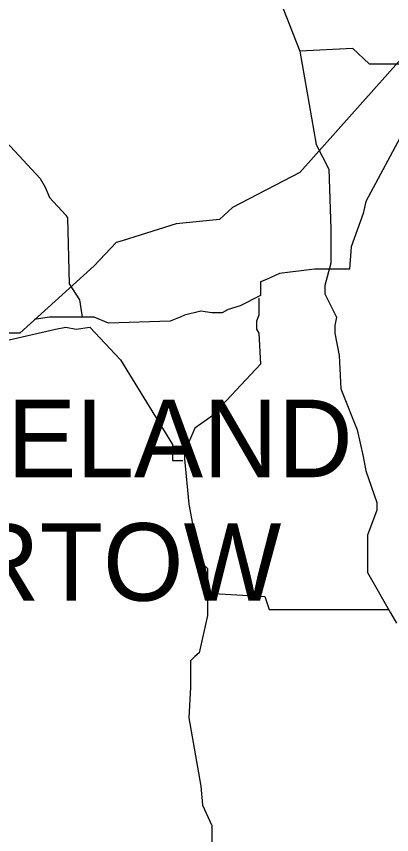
# Model space of a CAD drawing. Extents: x -827.9 to -798.1, y -2199.1 to -2182.2.
# Drawn here: x -806.0075 to -805.7896, y -2184.9111 to -2184.4362 of the extents above; entities that cross this region are included whole.
import ezdxf

# ---------------------------------------------------------------- set-up
doc = ezdxf.new("R2010")
doc.units = 0
for name, color, linetype in [('FLMap2', 7, 'Continuous'), ('FLMap3', 7, 'Continuous'), ('TextMisc', 7, 'Continuous')]:
    doc.layers.add(name, color=color, linetype=linetype)

msp = doc.modelspace()

# ---------------------------------------------------------------- linework, layer by layer
at = {"layer": 'FLMap2'}
for points in [[(-805.94057, -2184.20533), (-805.94057, -2184.22716), (-805.93709, -2184.24006), (-805.9356, -2184.2475), (-805.93015, -2184.25792), (-805.92519, -2184.28223), (-805.92519, -2184.28917), (-805.91576, -2184.2986), (-805.89393, -2184.30455), (-805.88351, -2184.3115), (-805.87408, -2184.35119), (-805.8726, -2184.35615), (-805.86218, -2184.38145), (-805.86218, -2184.38939), (-805.86416, -2184.4003), (-805.85622, -2184.42213), (-805.84283, -2184.45637), (-805.8334, -2184.51044), (-805.82596, -2184.52483), (-805.82497, -2184.55956)], [(-805.72822, -2184.32539), (-805.72227, -2184.33581), (-805.71979, -2184.34176), (-805.71632, -2184.34771), (-805.71632, -2184.36806), (-805.71632, -2184.39435), (-805.71979, -2184.40973), (-805.7188, -2184.47919), (-805.7188, -2184.48415), (-805.72326, -2184.48613), (-805.72475, -2184.49109), (-805.73269, -2184.50151), (-805.75601, -2184.50399), (-805.77734, -2184.49953), (-805.78181, -2184.50151), (-805.80463, -2184.54368), (-805.80612, -2184.55063), (-805.81306, -2184.56998), (-805.81405, -2184.58288), (-805.83439, -2184.58288), (-805.85474, -2184.58536), (-805.86218, -2184.58883)], [(-805.81207, -2184.45488), (-805.84283, -2184.45637)], [(-805.81207, -2184.45488), (-805.80264, -2184.46381), (-805.75452, -2184.46381), (-805.74956, -2184.46728), (-805.7436, -2184.47919), (-805.70937, -2184.47919), (-805.69002, -2184.49358), (-805.68605, -2184.50052)], [(-806.07452, -2184.46976), (-806.0135, -2184.50896), (-805.99365, -2184.53029), (-805.99067, -2184.53525), (-805.98819, -2184.5412), (-805.97877, -2184.55162), (-805.97777, -2184.55311), (-805.97678, -2184.59131)], [(-805.82497, -2184.55956), (-805.82497, -2184.5794), (-805.82844, -2184.5923), (-805.82844, -2184.59727), (-805.8215, -2184.61066), (-805.82249, -2184.61562), (-805.82249, -2184.62009), (-805.82001, -2184.63299), (-805.81902, -2184.65234), (-805.80959, -2184.67615), (-805.80612, -2184.69153), (-805.80463, -2184.69996), (-805.79818, -2184.71832), (-805.79818, -2184.72278), (-805.80364, -2184.73717), (-805.80364, -2184.759), (-805.79024, -2184.78232), (-805.78677, -2184.78827)], [(-805.86218, -2184.58883), (-805.86565, -2184.59032), (-805.86565, -2184.59826), (-805.87756, -2184.60421), (-805.8845, -2184.6062), (-805.88798, -2184.60818), (-805.89393, -2184.60818), (-805.90038, -2184.60719), (-805.90981, -2184.60967), (-805.91229, -2184.61066), (-805.91824, -2184.61314), (-805.95396, -2184.61413), (-805.9624, -2184.61066), (-805.98819, -2184.61066), (-805.99712, -2184.61215)], [(-805.97678, -2184.59131), (-805.97083, -2184.60074), (-805.96934, -2184.61066)], [(-805.86664, -2184.59975), (-805.86664, -2184.60967), (-805.86813, -2184.61314), (-805.86813, -2184.61761), (-805.86664, -2184.62009), (-805.86565, -2184.63795), (-805.89393, -2184.66821), (-805.90385, -2184.67516), (-805.90981, -2184.68905), (-805.90981, -2184.69401)], [(-806.14993, -2184.64291), (-806.14298, -2184.64291), (-806.11173, -2184.63547), (-806.0904, -2184.62852), (-806.04971, -2184.631), (-806.04376, -2184.62951), (-806.03632, -2184.62951), (-805.98472, -2184.61761), (-805.97877, -2184.61661), (-805.97281, -2184.61761), (-805.96488, -2184.61661), (-805.94702, -2184.63547), (-805.91675, -2184.68458), (-805.91675, -2184.69401), (-805.9108, -2184.69401)], [(-805.91675, -2184.68558), (-805.90981, -2184.68558)], [(-805.90981, -2184.69302), (-805.90733, -2184.71931), (-805.90137, -2184.75156), (-805.89641, -2184.75652), (-805.89641, -2184.78381)], [(-805.89641, -2184.77091), (-805.87954, -2184.7719), (-805.86317, -2184.77289), (-805.86069, -2184.78034), (-805.79123, -2184.78034)], [(-805.89641, -2184.78381), (-805.90137, -2184.80564), (-805.90385, -2184.80762), (-805.90633, -2184.8101), (-805.90633, -2184.82548), (-805.90733, -2184.84334), (-805.90038, -2184.88303), (-805.89939, -2184.89395), (-805.89393, -2184.90585), (-805.89393, -2184.95249), (-805.89294, -2184.9644), (-805.89641, -2184.98176), (-805.9108, -2185.01302), (-805.91923, -2185.03832)]]:
    msp.add_lwpolyline(points, dxfattribs=at)
at = {"layer": 'FLMap3'}
for points in [[(-805.57294, -2184.03962), (-805.59179, -2184.04806), (-805.62801, -2184.08874), (-805.64785, -2184.11206), (-805.66968, -2184.18548), (-805.69002, -2184.2088), (-805.71533, -2184.27627), (-805.71284, -2184.32638), (-805.70788, -2184.33482), (-805.71284, -2184.36309), (-805.71632, -2184.37202), (-805.72674, -2184.37401), (-805.75055, -2184.39782), (-805.75055, -2184.42313), (-805.84283, -2184.52682)], [(-805.84283, -2184.52682), (-805.88202, -2184.54716), (-805.88946, -2184.5541), (-805.91477, -2184.55658), (-805.94602, -2184.56651), (-805.9495, -2184.5675), (-805.9624, -2184.58089), (-806.00556, -2184.62009), (-806.04475, -2184.62009), (-806.05666, -2184.62505), (-806.09883, -2184.62604), (-806.11768, -2184.63447), (-806.14993, -2184.64291), (-806.15588, -2184.64291), (-806.17474, -2184.65829), (-806.19409, -2184.65978), (-806.19905, -2184.66325), (-806.22385, -2184.66573), (-806.25511, -2184.67764), (-806.27297, -2184.68458), (-806.29331, -2184.7074), (-806.29331, -2184.75404), (-806.29232, -2184.75553), (-806.28289, -2184.75553)]]:
    msp.add_lwpolyline(points, dxfattribs=at)

# ---------------------------------------------------------------- texts
at = {"layer": 'TextMisc'}
for s, p in [('LAKELAND', (-806.12655, -2184.70363)), ('BARTOW', (-806.11767, -2184.7753))]:
    msp.add_text(s, height=0.045, dxfattribs=at).set_placement(p)

doc.saveas('drawing.dxf')
